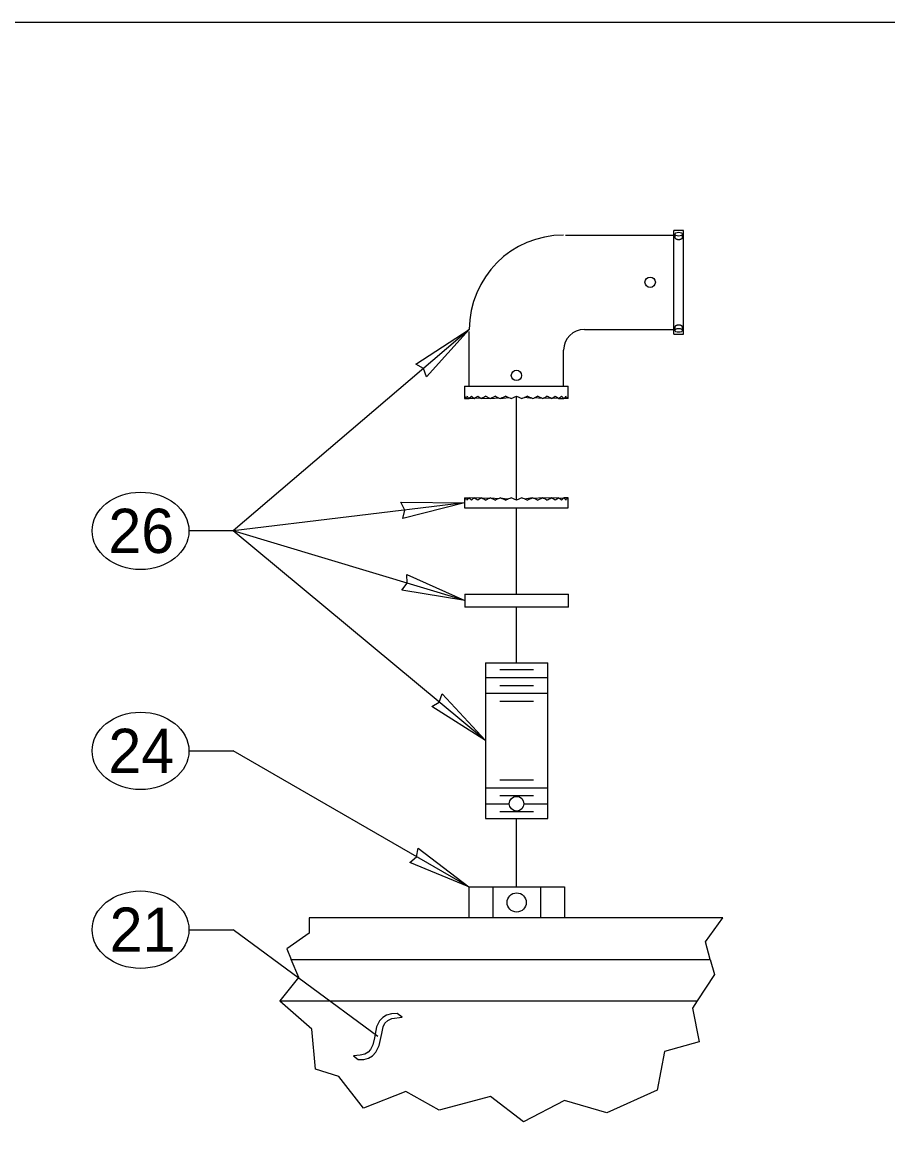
# Model space of a CAD drawing. Extents: x 99862 to 104211, y 98939 to 102076.
# Drawn here: x 100843.6 to 101156.4, y 101670.5 to 102075.5 of the extents above; entities that cross this region are included whole.
import ezdxf

# ---------------------------------------------------------------- set-up
doc = ezdxf.new("R2010")
doc.units = 0
for name, color, linetype in [('Level 1', 7, 'Continuous'), ('Level 15', 7, 'Continuous'), ('Level 16', 7, 'Continuous'), ('Level 2', 7, 'Continuous'), ('Level 20', 7, 'Continuous'), ('Level 22', 7, 'Continuous'), ('Level 25', 7, 'Continuous'), ('Level 27', 7, 'Continuous'), ('Level 6', 7, 'Continuous')]:
    doc.layers.add(name, color=color, linetype=linetype)

msp = doc.modelspace()

# ---------------------------------------------------------------- linework, layer by layer
at = {"layer": 'Level 1'}
msp.add_lwpolyline([(99862, 99999.5), (103151, 99999.5), (103151, 102075.5), (99862, 102075.5)], close=True, dxfattribs=at)
at = {"layer": 'Level 15'}
for p, q in [((101005.19, 101964.51), (100919.83, 101891.68)), ((101022.25, 101902.77), (101022.24, 101940.39)), ((101003.49, 101901.84), (100919.83, 101891.68)), ((101022.27, 101868.81), (101022.25, 101900.03)), ((100919.83, 101891.68), (100903.83, 101891.68)), ((101011.06, 101815.87), (100919.83, 101891.68)), ((101003.56, 101866.47), (100919.83, 101891.68)), ((101022.28, 101844), (101022.27, 101864.12)), ((100903.83, 101812.14), (100919.83, 101812.14)), ((101004.99, 101762.98), (100919.83, 101812.14)), ((101022.31, 101762.98), (101022.3, 101787.75)), ((100903.83, 101747.5), (100919.83, 101747.5)), ((100972.1, 101708.87), (100919.83, 101747.5)), ((100977.01, 101717.06), (100975.29, 101716.6)), ((100979.16, 101717.18), (100977.01, 101717.06)), ((100980.86, 101715.92), (100979.16, 101717.18)), ((100972.75, 101714.59), (100971.6, 101712.41)), ((100973.89, 101715.8), (100972.75, 101714.59)), ((100975.29, 101716.6), (100973.89, 101715.8)), ((100974, 101712.33), (100974.69, 101713.66)), ((100974.69, 101713.66), (100975.72, 101714.64)), ((100975.72, 101714.64), (100977.21, 101715.34)), ((100977.21, 101715.34), (100980.86, 101715.92)), ((100971.6, 101712.41), (100970.88, 101708.38)), ((100972.66, 101705.62), (100973.52, 101709.95)), ((100973.52, 101709.95), (100974, 101712.33)), ((100970.37, 101705.89), (100969.53, 101704.16)), ((100970.88, 101708.38), (100970.37, 101705.89)), ((100971.45, 101703.19), (100972.66, 101705.62)), ((100963.32, 101701.85), (100965.02, 101700.59)), ((100965.74, 101702.09), (100963.33, 101701.85)), ((100965.02, 101700.59), (100967.01, 101700.62)), ((100967.42, 101702.53), (100965.74, 101702.09)), ((100967.01, 101700.62), (100968.75, 101701.06)), ((100968.6, 101703.2), (100967.42, 101702.53)), ((100969.53, 101704.16), (100968.6, 101703.2)), ((100968.75, 101701.06), (100970.23, 101701.92)), ((100970.23, 101701.92), (100971.45, 101703.19))]:
    msp.add_line(p, q, dxfattribs=at)
for points in [[(101005.19, 101964.51), (100989.76, 101947.42), (100988.63, 101950.38), (100985.89, 101951.96)], [(101003.49, 101901.84), (100981.18, 101896.13), (100981.87, 101899.22), (100980.46, 101902.05)], [(101003.56, 101866.47), (100980.84, 101870.19), (100982.71, 101872.74), (100982.56, 101875.91)], [(101011.06, 101815.87), (100991.59, 101828.17), (100994.31, 101829.79), (100995.41, 101832.76)], [(101004.99, 101762.98), (100983.73, 101771.81), (100986.13, 101773.86), (100986.71, 101776.98)]]:
    msp.add_lwpolyline(points, close=True, dxfattribs=at)
at = {"layer": 'Level 16'}
for centre in [(101070.58, 101981.55), (101022.24, 101947.89)]:
    msp.add_circle(centre, 1.88, dxfattribs=at)
for centre in [(101080.89, 101998.94), (101080.89, 101964.16)]:
    msp.add_ellipse(centre, major_axis=(1.41, 0), ratio=0.5, dxfattribs=at)
at = {"layer": 'Level 2'}
for p, q in [((101003.56, 101868.81), (101041.06, 101868.81)), ((101003.56, 101868.81), (101003.56, 101864.12)), ((101041.06, 101864.12), (101041.06, 101868.81)), ((101041.06, 101864.12), (101003.56, 101864.12))]:
    msp.add_line(p, q, dxfattribs=at)
msp.add_circle((101022.27, 101793.03), 2.65, dxfattribs=at)
at = {"layer": 'Level 20'}
for centre in [(100886.33, 101891.68), (100886.33, 101812.14), (100886.33, 101747.5)]:
    msp.add_ellipse(centre, major_axis=(-17.5, 0), ratio=0.8, dxfattribs=at)
at = {"layer": 'Level 22'}
for p, q in [((101003.49, 101939.49), (101003.89, 101939.51)), ((101003.9, 101939.49), (101005.06, 101939.54)), ((101006.94, 101939.58), (101005.11, 101939.49)), ((101009.46, 101939.63), (101007.07, 101939.49)), ((101009.69, 101939.49), (101012.48, 101939.69)), ((101012.86, 101939.49), (101015.85, 101939.77)), ((101016.44, 101939.49), (101019.31, 101939.93)), ((101028.03, 101939.49), (101025.16, 101939.93)), ((101031.61, 101939.49), (101028.62, 101939.77)), ((101034.78, 101939.49), (101031.99, 101939.69)), ((101037.41, 101939.49), (101035.01, 101939.63)), ((101037.53, 101939.58), (101039.37, 101939.49)), ((101040.58, 101939.49), (101039.42, 101939.54)), ((101040.99, 101939.49), (101040.59, 101939.51)), ((101003.49, 101903.66), (101003.49, 101900.03)), ((101003.49, 101903.66), (101003.89, 101903.64)), ((101003.9, 101903.66), (101005.06, 101903.6)), ((101006.94, 101903.56), (101005.11, 101903.66)), ((101009.46, 101903.52), (101007.07, 101903.66)), ((101009.69, 101903.66), (101012.48, 101903.46)), ((101012.86, 101903.66), (101015.85, 101903.37)), ((101016.44, 101903.66), (101018.61, 101903.32)), ((101022.24, 101902.76), (101020.27, 101903.66)), ((101024.2, 101903.66), (101022.24, 101902.76)), ((101028.03, 101903.66), (101025.86, 101903.32)), ((101031.61, 101903.66), (101028.62, 101903.37)), ((101034.78, 101903.66), (101031.99, 101903.46)), ((101037.41, 101903.66), (101035.01, 101903.52)), ((101037.53, 101903.56), (101039.37, 101903.66)), ((101040.58, 101903.66), (101039.42, 101903.6)), ((101040.99, 101903.66), (101040.59, 101903.64)), ((101040.99, 101900.03), (101040.99, 101903.66)), ((101003.49, 101900.03), (101022.24, 101900.03)), ((101022.24, 101900.03), (101040.99, 101900.03)), ((101096.88, 101751.73), (100947.33, 101751.73)), ((100947.33, 101751.73), (100947.33, 101746.22)), ((101090.57, 101743.12), (101096.88, 101751.73)), ((100947.33, 101746.22), (100939.17, 101740.53)), ((101092.3, 101736.73), (101090.57, 101743.12)), ((100939.17, 101740.53), (100940.82, 101736.73)), ((100940.82, 101736.73), (101092.3, 101736.73)), ((100943.62, 101730.26), (100940.82, 101736.73)), ((101092.3, 101736.73), (101093.79, 101731.25)), ((100936.8, 101721.73), (100943.62, 101730.26)), ((101093.79, 101731.25), (101087.57, 101721.73)), ((100936.7, 101721.6), (100936.8, 101721.73)), ((100948.32, 101711.58), (100936.7, 101721.6)), ((100936.8, 101721.73), (101087.57, 101721.73)), ((101087.57, 101721.73), (101085.87, 101719.13)), ((101085.87, 101719.13), (101088.34, 101707)), ((100949.56, 101697.11), (100948.32, 101711.58)), ((101088.34, 101707), (101075.73, 101703.42)), ((101075.73, 101703.42), (101073.13, 101689.44)), ((100957.97, 101694.39), (100949.56, 101697.11)), ((100966.88, 101683.01), (100957.97, 101694.39)), ((100982.22, 101688.95), (100966.88, 101683.01)), ((100994.34, 101682.27), (100982.22, 101688.95)), ((101073.13, 101689.44), (101054.95, 101681.28)), ((101012.89, 101687.21), (100994.34, 101682.27)), ((101024.77, 101678.06), (101012.89, 101687.21)), ((101039.61, 101685.73), (101024.77, 101678.06)), ((101054.95, 101681.28), (101039.61, 101685.73))]:
    msp.add_line(p, q, dxfattribs=at)
for major_axis, ratio, start_param, end_param in [((-18.74, 1.13), 0.454735, 0.027493, 0.132213), ((18.74, 1.13), 0.454735, 2.90466, 3.00938), ((-18.7, 3.25), 0.425627, 0.283365, 0.388085), ((18.7, 3.25), 0.425627, 2.648788, 2.753508), ((-18.66, 5.02), 0.374036, 0.519261, 0.623981), ((18.66, 5.02), 0.374036, 2.412892, 2.517611), ((-18.65, 6.39), 0.308341, 0.733647, 0.838367), ((18.65, 6.39), 0.308341, 2.198506, 2.303225), ((-18.67, 7.39), 0.235006, 0.930571, 1.035291), ((18.67, 7.39), 0.235006, 2.001582, 2.106302), ((-18.71, 8.07), 0.157954, 1.115271, 1.219991), ((18.71, 8.07), 0.157954, 1.816882, 1.921602), ((-18.74, 8.47), 0.079271, 1.292449, 1.397169), ((18.74, 8.47), 0.079271, 1.64005, 1.744424), ((11.71, -5.29), 0.079271, 4.434042, 4.47487), ((-18.74, 8.47), 0.079271, 4.538761, 4.643136), ((-11.71, -5.29), 0.079271, 1.808316, 1.849144), ((18.74, 8.47), 0.079271, 4.886017, 4.990736), ((-18.71, 8.07), 0.157954, 4.361583, 4.466303), ((18.71, 8.07), 0.157954, 5.063195, 5.167914), ((-18.67, 7.39), 0.235006, 4.176883, 4.281603), ((18.67, 7.39), 0.235006, 5.247895, 5.352614), ((-18.65, 6.39), 0.308341, 3.97996, 4.08468), ((18.65, 6.39), 0.308341, 5.444818, 5.549538), ((-18.66, 5.02), 0.374036, 3.765574, 3.870294), ((18.66, 5.02), 0.374036, 5.659204, 5.763924), ((-18.7, 3.25), 0.425627, 3.529678, 3.634397), ((18.7, 3.25), 0.425627, 5.8951, 5.99982), ((-18.74, 1.13), 0.454735, 3.273805, 3.378525), ((18.74, 1.13), 0.454735, 6.150973, 6.255692)]:
    msp.add_ellipse((101022.24, 101902.76), major_axis=major_axis, ratio=ratio, start_param=start_param, end_param=end_param, dxfattribs=at)
at = {"layer": 'Level 25'}
for p, q in [((101004.99, 101762.98), (101004.99, 101751.73)), ((101004.99, 101762.98), (101013.65, 101762.98)), ((101013.65, 101762.98), (101030.97, 101762.98)), ((101030.97, 101762.98), (101039.63, 101762.98)), ((101039.63, 101762.98), (101039.63, 101751.73))]:
    msp.add_line(p, q, dxfattribs=at)
at = {"layer": 'Level 27'}
for p, q in [((101082.59, 101962.8), (101082.59, 102000.3)), ((101040.01, 101998.6), (101079.18, 101998.6)), ((101005.19, 101944.05), (101005.19, 101963.78)), ((101046.78, 101964.51), (101079.18, 101964.51)), ((101039.28, 101944.05), (101039.28, 101957.01)), ((101011.06, 101844), (101011.06, 101787.75)), ((101011.06, 101844), (101033.56, 101844)), ((101033.56, 101787.75), (101033.56, 101844)), ((101011.02, 101838.72), (101033.52, 101838.72)), ((101016.18, 101841.51), (101028.44, 101841.51)), ((101016.18, 101835.76), (101028.44, 101835.76)), ((101011.02, 101832.97), (101033.52, 101832.97)), ((101016.18, 101830.08), (101028.44, 101830.08)), ((101011.02, 101798.77), (101033.52, 101798.77)), ((101016.18, 101801.67), (101028.44, 101801.67)), ((101016.18, 101795.98), (101028.44, 101795.98)), ((101011.02, 101793.03), (101019.62, 101793.03)), ((101016.18, 101790.24), (101028.44, 101790.24)), ((101024.92, 101793.03), (101033.52, 101793.03)), ((101011.06, 101787.75), (101033.56, 101787.75)), ((101013.65, 101762.98), (101013.65, 101751.73)), ((101030.97, 101762.98), (101030.97, 101751.73))]:
    msp.add_line(p, q, dxfattribs=at)
msp.add_circle((101022.31, 101757.35), 3.46, dxfattribs=at)
for centre, radius in [((101039.28, 101964.51), 34.09), ((101046.78, 101957.01), 7.5)]:
    msp.add_arc(centre, radius, 90, 180, dxfattribs=at)
at = {"layer": 'Level 6'}
for p, q in [((101079.18, 101962.8), (101079.18, 102000.3)), ((101082.59, 102000.3), (101079.18, 102000.3)), ((101079.48, 101998.94), (101079.48, 101997.83)), ((101082.29, 101997.83), (101082.29, 101998.94)), ((101079.48, 101965.32), (101079.48, 101964.16)), ((101082.29, 101964.16), (101082.29, 101965.27)), ((101079.18, 101962.8), (101082.59, 101962.8)), ((101003.49, 101944.05), (101040.99, 101944.05)), ((101003.49, 101944.05), (101003.49, 101939.49)), ((101040.99, 101939.49), (101040.99, 101944.05)), ((101020.28, 101939.49), (101022.24, 101940.39)), ((101022.24, 101940.39), (101024.2, 101939.49))]:
    msp.add_line(p, q, dxfattribs=at)
for major_axis, ratio, start_param, end_param in [((-18.74, -1.13), 0.454735, 6.150973, 6.255692), ((18.74, -1.13), 0.454735, 3.273805, 3.378525), ((-18.7, -3.25), 0.425627, 5.8951, 5.99982), ((18.7, -3.25), 0.425627, 3.529678, 3.634052), ((-18.66, -4.98), 0.371913, 5.660629, 5.765694), ((18.7, -3.25), 0.425627, 3.634052, 3.634397), ((-18.66, -5.02), 0.374036, 5.763545, 5.763924), ((18.66, -4.98), 0.371913, 3.764149, 3.869214), ((18.66, -5.02), 0.374036, 3.858727, 3.870294), ((-18.65, -6.39), 0.308341, 5.444818, 5.549192), ((-18.65, -6.39), 0.308341, 5.549192, 5.549538), ((18.65, -6.39), 0.308341, 3.97996, 4.08468), ((-18.67, -7.39), 0.235006, 5.247895, 5.352614), ((18.67, -7.39), 0.235006, 4.176883, 4.281603), ((-18.71, -8.07), 0.157954, 5.063195, 5.167914), ((18.71, -8.07), 0.157954, 4.361583, 4.466303), ((-18.74, -8.47), 0.079271, 4.886017, 4.990736), ((18.74, -8.47), 0.079271, 4.538761, 4.643481), ((-18.74, -8.47), 0.079271, 1.639704, 1.744424), ((18.74, -8.47), 0.079271, 1.292449, 1.397169), ((-18.71, -8.07), 0.157954, 1.816882, 1.921602), ((18.71, -8.07), 0.157954, 1.115271, 1.219991), ((-18.67, -7.39), 0.235006, 2.001582, 2.106302), ((18.67, -7.39), 0.235006, 0.930571, 1.035291), ((-18.65, -6.39), 0.308341, 2.198506, 2.303225), ((18.65, -6.39), 0.308341, 0.733647, 0.838367), ((-18.66, -5.02), 0.374036, 2.412892, 2.517611), ((18.66, -5.02), 0.374036, 0.519261, 0.623981), ((-18.7, -3.25), 0.425627, 2.648788, 2.753508), ((18.7, -3.25), 0.425627, 0.283365, 0.388085), ((-18.74, -1.13), 0.454735, 2.90466, 3.00938), ((18.74, -1.13), 0.454735, 0.027493, 0.132213)]:
    msp.add_ellipse((101022.24, 101940.39), major_axis=major_axis, ratio=ratio, start_param=start_param, end_param=end_param, dxfattribs=at)
for points in [[(101079.48, 101997.83), (101079.48, 101997.77), (101079.49, 101997.7), (101079.52, 101997.63), (101079.55, 101997.55), (101079.61, 101997.48), (101079.7, 101997.4), (101079.78, 101997.33), (101079.89, 101997.27), (101080.01, 101997.21), (101080.13, 101997.16), (101080.28, 101997.12), (101080.42, 101997.09), (101080.57, 101997.06), (101080.73, 101997.04), (101080.89, 101997.04)], [(101080.89, 101997.04), (101080.99, 101997.04), (101081.09, 101997.05), (101081.19, 101997.06), (101081.34, 101997.08), (101081.49, 101997.11), (101081.63, 101997.16), (101081.76, 101997.21), (101081.88, 101997.26), (101081.98, 101997.33), (101082.08, 101997.4), (101082.16, 101997.47), (101082.21, 101997.55), (101082.27, 101997.63), (101082.29, 101997.71), (101082.29, 101997.79), (101082.29, 101997.8), (101082.29, 101997.81), (101082.29, 101997.83)], [(101082.29, 101965.27), (101082.29, 101965.29), (101082.29, 101965.3), (101082.29, 101965.31), (101082.3, 101965.39), (101082.27, 101965.47), (101082.22, 101965.55), (101082.17, 101965.63), (101082.09, 101965.7), (101081.99, 101965.77), (101081.89, 101965.84), (101081.77, 101965.9), (101081.64, 101965.94), (101081.51, 101965.99), (101081.36, 101966.02), (101081.21, 101966.04), (101081.05, 101966.06), (101080.89, 101966.07), (101080.74, 101966.06), (101080.58, 101966.05), (101080.42, 101966.03), (101080.28, 101965.99), (101080.14, 101965.95), (101080.01, 101965.9), (101079.9, 101965.84), (101079.79, 101965.78), (101079.69, 101965.71), (101079.62, 101965.63), (101079.55, 101965.56), (101079.51, 101965.48), (101079.49, 101965.4), (101079.49, 101965.37), (101079.48, 101965.34), (101079.48, 101965.32)]]:
    msp.add_open_spline(points, degree=3, dxfattribs=at)

# ---------------------------------------------------------------- texts
at = {"layer": 'Level 20'}
for s, p in [('26', (100874.7, 101883.68)), ('24', (100874.7, 101804.14)), ('21', (100875.15, 101739.5))]:
    msp.add_text(s, height=16, dxfattribs=at).set_placement(p)

doc.saveas('drawing.dxf')
